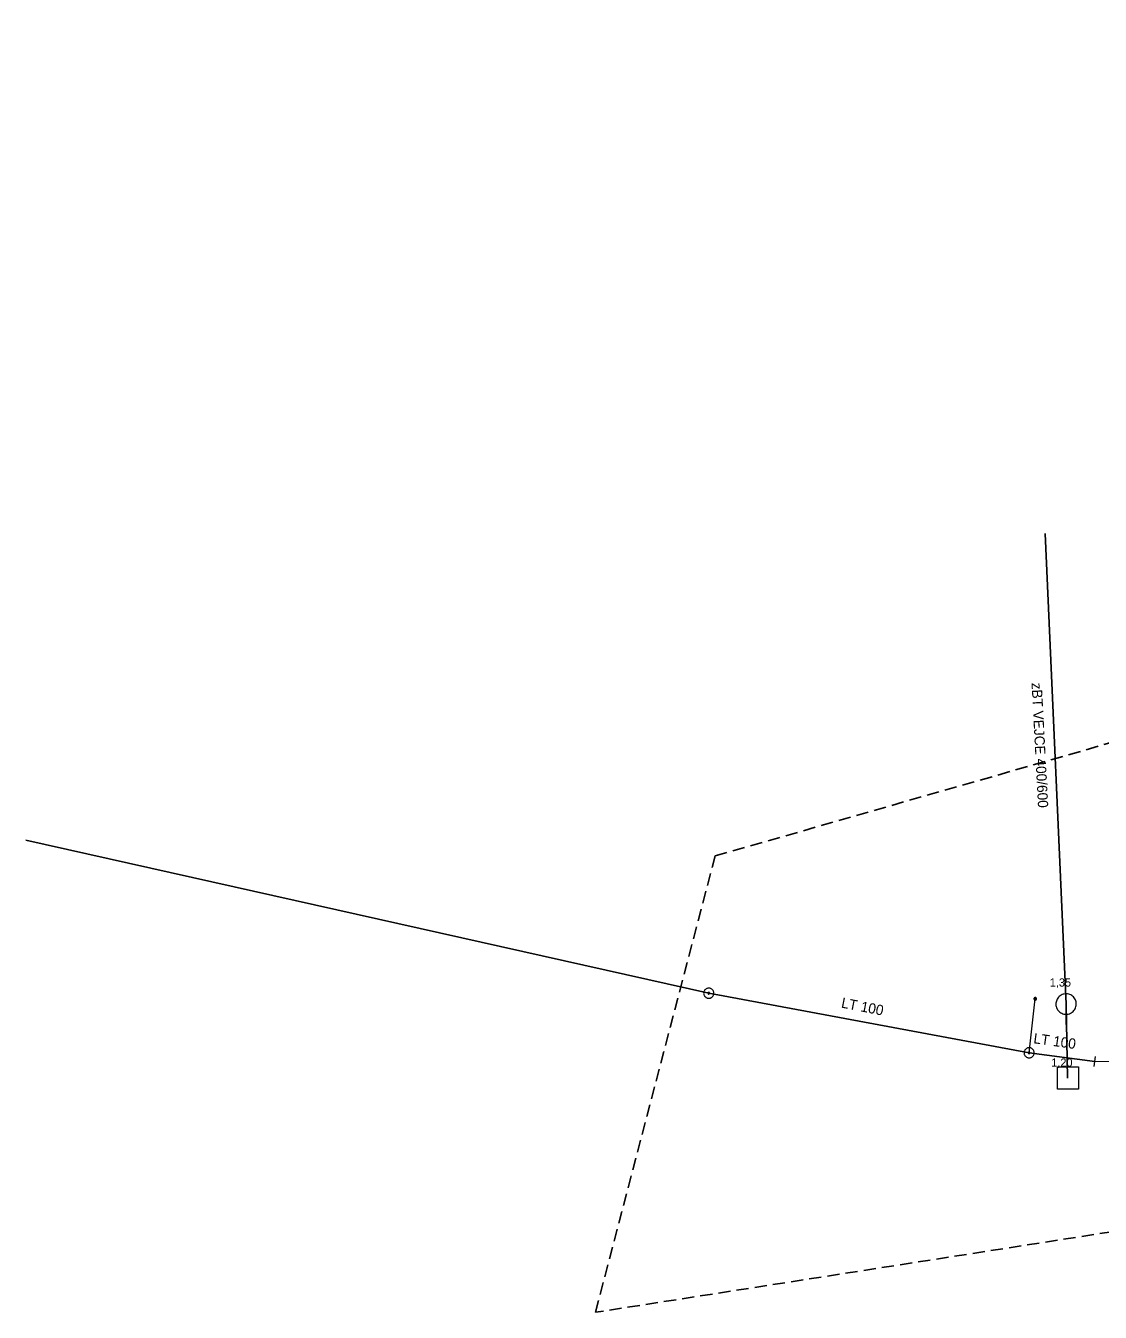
# Model space of a CAD drawing. Extents: x -689820 to -689363, y -975369 to -975062.
# Drawn here: x -689820.1 to -689714.8, y -975341.6 to -975215.7 of the extents above; entities that cross this region are included whole.
import ezdxf

# ---------------------------------------------------------------- set-up
doc = ezdxf.new("R2010")
doc.units = 0
doc.header["$LTSCALE"] = 0.4
doc.linetypes.add('MEDIUM_DASHED', pattern=[4.5, 3, -1.5])
doc.layers.add('1', color=7, linetype='Continuous')
for name, color, linetype, lineweight in [('14', 7, 'Continuous', 25), ('17', 7, 'Continuous', 25), ('22', 7, 'Continuous', 13), ('34', 7, 'Continuous', 13), ('47', 7, 'Continuous', 13), ('63', 7, 'MEDIUM_DASHED', 25), ('9', 7, 'Continuous', 13)]:
    doc.layers.add(name, color=color, linetype=linetype, lineweight=lineweight)

msp = doc.modelspace()

# ---------------------------------------------------------------- linework, layer by layer
at = {"layer": '14'}
for p, q in [((-689718.193, -975311.442), (-689720.241, -975265.388)), ((-689718.046, -975318.682), (-689718.193, -975311.442))]:
    msp.add_line(p, q, dxfattribs=at)
at = {"layer": '14', "lineweight": 13}
for p, q in [((-689721.813, -975316.213), (-689721.219, -975310.929)), ((-689713.89, -975317.113), (-689715.37, -975317.07))]:
    msp.add_line(p, q, dxfattribs=at)
at = {"layer": '17'}
for p, q in [((-689753.181, -975310.38), (-689820.059, -975295.399)), ((-689721.813, -975316.213), (-689753.181, -975310.38)), ((-689715.37, -975317.07), (-689721.813, -975316.213))]:
    msp.add_line(p, q, dxfattribs=at)
at = {"layer": '22'}
msp.add_line((-689718.193, -975313.442), (-689718.192, -975310.442), dxfattribs=at)
for points in [[(-689717.193, -975311.442), (-689717.198, -975311.333), (-689717.216, -975311.225), (-689717.246, -975311.119), (-689717.286, -975311.018), (-689717.338, -975310.921), (-689717.4, -975310.831), (-689717.472, -975310.748), (-689717.552, -975310.674), (-689717.64, -975310.608), (-689717.734, -975310.553), (-689717.834, -975310.508), (-689717.939, -975310.475), (-689718.046, -975310.453), (-689718.155, -975310.443), (-689718.265, -975310.445), (-689718.373, -975310.459), (-689718.48, -975310.484), (-689718.583, -975310.521), (-689718.681, -975310.57), (-689718.773, -975310.628), (-689718.859, -975310.697), (-689718.936, -975310.774), (-689719.005, -975310.86), (-689719.064, -975310.952), (-689719.112, -975311.05), (-689719.149, -975311.153), (-689719.175, -975311.26), (-689719.189, -975311.368), (-689719.192, -975311.478), (-689719.182, -975311.587), (-689719.161, -975311.694), (-689719.127, -975311.798), (-689719.083, -975311.898), (-689719.028, -975311.993), (-689718.962, -975312.081), (-689718.888, -975312.161), (-689718.805, -975312.233), (-689718.715, -975312.295), (-689718.619, -975312.347), (-689718.517, -975312.388), (-689718.412, -975312.418), (-689718.304, -975312.436), (-689718.194, -975312.442), (-689718.085, -975312.436), (-689717.977, -975312.418), (-689717.872, -975312.389), (-689717.77, -975312.348), (-689717.673, -975312.296), (-689717.583, -975312.234), (-689717.5, -975312.163), (-689717.425, -975312.083), (-689717.36, -975311.995), (-689717.304, -975311.901), (-689717.26, -975311.801), (-689717.226, -975311.697), (-689717.204, -975311.589), (-689717.194, -975311.48)], [(-689719.026, -975317.592), (-689716.993, -975317.592), (-689716.993, -975319.785), (-689719.026, -975319.785)]]:
    msp.add_lwpolyline(points, close=True, dxfattribs=at)
at = {"layer": '34'}
msp.add_line((-689715.435, -975317.565), (-689715.303, -975316.574), dxfattribs=at)
at = {"layer": '47'}
for points in [[(-689752.681, -975310.38), (-689752.684, -975310.328), (-689752.692, -975310.276), (-689752.706, -975310.226), (-689752.723, -975310.177), (-689752.748, -975310.13), (-689752.777, -975310.086), (-689752.809, -975310.046), (-689752.847, -975310.009), (-689752.887, -975309.976), (-689752.931, -975309.947), (-689752.978, -975309.923), (-689753.027, -975309.905), (-689753.076, -975309.891), (-689753.129, -975309.883), (-689753.181, -975309.88), (-689753.233, -975309.883), (-689753.285, -975309.891), (-689753.336, -975309.905), (-689753.384, -975309.923), (-689753.431, -975309.947), (-689753.475, -975309.976), (-689753.516, -975310.009), (-689753.553, -975310.046), (-689753.586, -975310.086), (-689753.614, -975310.13), (-689753.638, -975310.177), (-689753.657, -975310.226), (-689753.669, -975310.276), (-689753.678, -975310.328), (-689753.681, -975310.38), (-689753.678, -975310.432), (-689753.669, -975310.484), (-689753.657, -975310.535), (-689753.638, -975310.583), (-689753.614, -975310.63), (-689753.586, -975310.674), (-689753.553, -975310.715), (-689753.516, -975310.752), (-689753.475, -975310.785), (-689753.431, -975310.813), (-689753.384, -975310.837), (-689753.336, -975310.856), (-689753.285, -975310.869), (-689753.233, -975310.877), (-689753.181, -975310.88), (-689753.129, -975310.877), (-689753.076, -975310.869), (-689753.027, -975310.856), (-689752.978, -975310.837), (-689752.931, -975310.813), (-689752.887, -975310.785), (-689752.847, -975310.752), (-689752.809, -975310.715), (-689752.777, -975310.674), (-689752.748, -975310.63), (-689752.723, -975310.583), (-689752.706, -975310.535), (-689752.692, -975310.484), (-689752.684, -975310.432)], [(-689753.098, -975310.38), (-689753.098, -975310.371), (-689753.101, -975310.363), (-689753.103, -975310.355), (-689753.106, -975310.347), (-689753.11, -975310.339), (-689753.115, -975310.332), (-689753.12, -975310.325), (-689753.125, -975310.319), (-689753.133, -975310.314), (-689753.14, -975310.309), (-689753.147, -975310.305), (-689753.156, -975310.302), (-689753.164, -975310.3), (-689753.172, -975310.298), (-689753.181, -975310.298), (-689753.19, -975310.298), (-689753.198, -975310.3), (-689753.206, -975310.302), (-689753.214, -975310.305), (-689753.222, -975310.309), (-689753.228, -975310.314), (-689753.236, -975310.319), (-689753.242, -975310.325), (-689753.248, -975310.332), (-689753.252, -975310.339), (-689753.255, -975310.347), (-689753.259, -975310.355), (-689753.261, -975310.363), (-689753.263, -975310.371), (-689753.263, -975310.38), (-689753.263, -975310.389), (-689753.261, -975310.397), (-689753.259, -975310.405), (-689753.255, -975310.413), (-689753.252, -975310.421), (-689753.248, -975310.428), (-689753.242, -975310.435), (-689753.236, -975310.441), (-689753.228, -975310.447), (-689753.222, -975310.451), (-689753.214, -975310.455), (-689753.206, -975310.458), (-689753.198, -975310.46), (-689753.19, -975310.462), (-689753.181, -975310.462), (-689753.172, -975310.462), (-689753.164, -975310.46), (-689753.156, -975310.458), (-689753.147, -975310.455), (-689753.14, -975310.451), (-689753.133, -975310.447), (-689753.125, -975310.441), (-689753.12, -975310.435), (-689753.115, -975310.428), (-689753.11, -975310.421), (-689753.106, -975310.413), (-689753.103, -975310.405), (-689753.101, -975310.397), (-689753.098, -975310.389)], [(-689721.313, -975316.213), (-689721.316, -975316.161), (-689721.324, -975316.108), (-689721.338, -975316.059), (-689721.355, -975316.01), (-689721.38, -975315.963), (-689721.409, -975315.919), (-689721.441, -975315.879), (-689721.478, -975315.842), (-689721.519, -975315.809), (-689721.563, -975315.78), (-689721.61, -975315.755), (-689721.659, -975315.738), (-689721.708, -975315.724), (-689721.761, -975315.716), (-689721.813, -975315.713), (-689721.865, -975315.716), (-689721.917, -975315.724), (-689721.968, -975315.738), (-689722.016, -975315.755), (-689722.063, -975315.78), (-689722.107, -975315.809), (-689722.147, -975315.842), (-689722.184, -975315.879), (-689722.218, -975315.919), (-689722.245, -975315.963), (-689722.27, -975316.01), (-689722.289, -975316.059), (-689722.301, -975316.108), (-689722.309, -975316.161), (-689722.313, -975316.213), (-689722.309, -975316.265), (-689722.301, -975316.317), (-689722.289, -975316.368), (-689722.27, -975316.416), (-689722.245, -975316.463), (-689722.218, -975316.507), (-689722.184, -975316.548), (-689722.147, -975316.585), (-689722.107, -975316.618), (-689722.063, -975316.646), (-689722.016, -975316.67), (-689721.968, -975316.689), (-689721.917, -975316.701), (-689721.865, -975316.71), (-689721.813, -975316.713), (-689721.761, -975316.71), (-689721.708, -975316.701), (-689721.659, -975316.689), (-689721.61, -975316.67), (-689721.563, -975316.646), (-689721.519, -975316.618), (-689721.478, -975316.585), (-689721.441, -975316.548), (-689721.409, -975316.507), (-689721.38, -975316.463), (-689721.355, -975316.416), (-689721.338, -975316.368), (-689721.324, -975316.317), (-689721.316, -975316.265)], [(-689721.73, -975316.213), (-689721.73, -975316.204), (-689721.733, -975316.196), (-689721.735, -975316.188), (-689721.738, -975316.179), (-689721.742, -975316.172), (-689721.747, -975316.165), (-689721.752, -975316.157), (-689721.757, -975316.152), (-689721.765, -975316.147), (-689721.772, -975316.142), (-689721.779, -975316.138), (-689721.788, -975316.135), (-689721.796, -975316.133), (-689721.804, -975316.13), (-689721.813, -975316.13), (-689721.821, -975316.13), (-689721.83, -975316.133), (-689721.838, -975316.135), (-689721.846, -975316.138), (-689721.853, -975316.142), (-689721.86, -975316.147), (-689721.868, -975316.152), (-689721.874, -975316.157), (-689721.88, -975316.165), (-689721.884, -975316.172), (-689721.887, -975316.179), (-689721.891, -975316.188), (-689721.892, -975316.196), (-689721.895, -975316.204), (-689721.895, -975316.213), (-689721.895, -975316.222), (-689721.892, -975316.23), (-689721.891, -975316.238), (-689721.887, -975316.246), (-689721.884, -975316.254), (-689721.88, -975316.261), (-689721.874, -975316.268), (-689721.868, -975316.274), (-689721.86, -975316.28), (-689721.853, -975316.284), (-689721.846, -975316.288), (-689721.838, -975316.291), (-689721.83, -975316.293), (-689721.821, -975316.295), (-689721.813, -975316.295), (-689721.804, -975316.295), (-689721.796, -975316.293), (-689721.788, -975316.291), (-689721.779, -975316.288), (-689721.772, -975316.284), (-689721.765, -975316.28), (-689721.757, -975316.274), (-689721.752, -975316.268), (-689721.747, -975316.261), (-689721.742, -975316.254), (-689721.738, -975316.246), (-689721.735, -975316.238), (-689721.733, -975316.23), (-689721.73, -975316.222)]]:
    msp.add_lwpolyline(points, close=True, dxfattribs=at)
at = {"layer": '63'}
msp.add_lwpolyline([(-689662.123, -975114.404), (-689588.993, -975102.123), (-689588.993, -975102.123), (-689580.62, -975185.301), (-689580.62, -975185.301), (-689519.213, -975267.921), (-689519.213, -975267.921), (-689394.167, -975240.009), (-689394.167, -975240.009), (-689384.677, -975282.435), (-689384.677, -975282.435), (-689764.282, -975341.609), (-689764.282, -975341.609), (-689752.559, -975296.95), (-689752.559, -975296.95), (-689602.391, -975253.965), (-689627.512, -975210.422), (-689603.508, -975253.965), (-689648.167, -975167.437), (-689648.167, -975167.437)], close=True, dxfattribs=at)
at = {"layer": '9'}
for points in [[(-689721.345, -975310.929), (-689721.345, -975310.942), (-689721.343, -975310.955), (-689721.34, -975310.968), (-689721.335, -975310.98), (-689721.329, -975310.992), (-689721.322, -975311.003), (-689721.314, -975311.013), (-689721.304, -975311.023), (-689721.294, -975311.031), (-689721.283, -975311.038), (-689721.271, -975311.044), (-689721.259, -975311.049), (-689721.246, -975311.052), (-689721.233, -975311.054), (-689721.22, -975311.056), (-689721.207, -975311.055), (-689721.194, -975311.053), (-689721.181, -975311.05), (-689721.169, -975311.045), (-689721.157, -975311.039), (-689721.146, -975311.032), (-689721.136, -975311.024), (-689721.126, -975311.014), (-689721.118, -975311.004), (-689721.111, -975310.993), (-689721.105, -975310.981), (-689721.1, -975310.969), (-689721.097, -975310.956), (-689721.095, -975310.943), (-689721.093, -975310.93), (-689721.094, -975310.917), (-689721.096, -975310.904), (-689721.099, -975310.891), (-689721.104, -975310.879), (-689721.11, -975310.867), (-689721.117, -975310.856), (-689721.125, -975310.846), (-689721.135, -975310.836), (-689721.145, -975310.828), (-689721.156, -975310.821), (-689721.168, -975310.815), (-689721.18, -975310.81), (-689721.193, -975310.807), (-689721.206, -975310.805), (-689721.219, -975310.804), (-689721.232, -975310.804), (-689721.245, -975310.806), (-689721.258, -975310.809), (-689721.27, -975310.814), (-689721.282, -975310.82), (-689721.293, -975310.827), (-689721.303, -975310.835), (-689721.313, -975310.845), (-689721.321, -975310.855), (-689721.328, -975310.866), (-689721.334, -975310.878), (-689721.339, -975310.89), (-689721.342, -975310.903), (-689721.344, -975310.916)], [(-689721.325, -975310.929), (-689721.326, -975310.94), (-689721.324, -975310.951), (-689721.321, -975310.962), (-689721.317, -975310.972), (-689721.312, -975310.982), (-689721.306, -975310.991), (-689721.299, -975311), (-689721.291, -975311.008), (-689721.282, -975311.015), (-689721.273, -975311.021), (-689721.263, -975311.026), (-689721.253, -975311.03), (-689721.242, -975311.033), (-689721.231, -975311.036), (-689721.22, -975311.036), (-689721.209, -975311.036), (-689721.198, -975311.034), (-689721.187, -975311.031), (-689721.177, -975311.027), (-689721.167, -975311.022), (-689721.158, -975311.016), (-689721.149, -975311.009), (-689721.141, -975311.001), (-689721.134, -975310.992), (-689721.128, -975310.983), (-689721.123, -975310.973), (-689721.119, -975310.963), (-689721.116, -975310.952), (-689721.114, -975310.941), (-689721.113, -975310.93), (-689721.113, -975310.919), (-689721.115, -975310.908), (-689721.118, -975310.897), (-689721.122, -975310.887), (-689721.127, -975310.877), (-689721.133, -975310.868), (-689721.14, -975310.859), (-689721.148, -975310.851), (-689721.157, -975310.844), (-689721.166, -975310.838), (-689721.176, -975310.833), (-689721.186, -975310.829), (-689721.197, -975310.826), (-689721.208, -975310.824), (-689721.219, -975310.824), (-689721.23, -975310.823), (-689721.241, -975310.825), (-689721.252, -975310.828), (-689721.262, -975310.832), (-689721.272, -975310.837), (-689721.281, -975310.843), (-689721.29, -975310.85), (-689721.298, -975310.858), (-689721.305, -975310.867), (-689721.311, -975310.876), (-689721.316, -975310.886), (-689721.32, -975310.896), (-689721.323, -975310.907), (-689721.325, -975310.918)], [(-689721.306, -975310.929), (-689721.306, -975310.938), (-689721.305, -975310.947), (-689721.302, -975310.956), (-689721.299, -975310.964), (-689721.295, -975310.972), (-689721.29, -975310.98), (-689721.284, -975310.987), (-689721.278, -975310.993), (-689721.271, -975310.999), (-689721.263, -975311.004), (-689721.255, -975311.008), (-689721.247, -975311.011), (-689721.238, -975311.014), (-689721.229, -975311.015), (-689721.22, -975311.017), (-689721.211, -975311.016), (-689721.202, -975311.015), (-689721.193, -975311.012), (-689721.185, -975311.009), (-689721.177, -975311.005), (-689721.169, -975311), (-689721.162, -975310.994), (-689721.156, -975310.988), (-689721.15, -975310.981), (-689721.145, -975310.973), (-689721.141, -975310.965), (-689721.138, -975310.957), (-689721.135, -975310.948), (-689721.134, -975310.939), (-689721.132, -975310.93), (-689721.133, -975310.921), (-689721.134, -975310.912), (-689721.137, -975310.903), (-689721.14, -975310.895), (-689721.144, -975310.887), (-689721.149, -975310.879), (-689721.155, -975310.872), (-689721.161, -975310.866), (-689721.168, -975310.86), (-689721.176, -975310.855), (-689721.184, -975310.851), (-689721.192, -975310.848), (-689721.201, -975310.845), (-689721.21, -975310.844), (-689721.219, -975310.843), (-689721.228, -975310.843), (-689721.237, -975310.844), (-689721.246, -975310.847), (-689721.254, -975310.85), (-689721.262, -975310.854), (-689721.27, -975310.859), (-689721.277, -975310.865), (-689721.283, -975310.871), (-689721.289, -975310.878), (-689721.294, -975310.886), (-689721.298, -975310.894), (-689721.301, -975310.902), (-689721.304, -975310.911), (-689721.305, -975310.92)], [(-689721.286, -975310.929), (-689721.286, -975310.936), (-689721.285, -975310.943), (-689721.284, -975310.95), (-689721.281, -975310.956), (-689721.278, -975310.962), (-689721.274, -975310.968), (-689721.27, -975310.974), (-689721.265, -975310.979), (-689721.259, -975310.983), (-689721.253, -975310.987), (-689721.247, -975310.99), (-689721.241, -975310.993), (-689721.234, -975310.994), (-689721.227, -975310.997), (-689721.22, -975310.997), (-689721.213, -975310.997), (-689721.206, -975310.995), (-689721.199, -975310.994), (-689721.193, -975310.991), (-689721.186, -975310.988), (-689721.181, -975310.984), (-689721.175, -975310.98), (-689721.17, -975310.975), (-689721.166, -975310.969), (-689721.162, -975310.963), (-689721.159, -975310.957), (-689721.156, -975310.951), (-689721.154, -975310.944), (-689721.153, -975310.937), (-689721.152, -975310.93), (-689721.152, -975310.923), (-689721.153, -975310.916), (-689721.155, -975310.909), (-689721.158, -975310.903), (-689721.161, -975310.896), (-689721.165, -975310.891), (-689721.169, -975310.885), (-689721.174, -975310.88), (-689721.18, -975310.876), (-689721.185, -975310.872), (-689721.192, -975310.869), (-689721.198, -975310.866), (-689721.205, -975310.864), (-689721.212, -975310.863), (-689721.219, -975310.863), (-689721.226, -975310.863), (-689721.233, -975310.863), (-689721.24, -975310.865), (-689721.246, -975310.868), (-689721.252, -975310.871), (-689721.258, -975310.875), (-689721.264, -975310.879), (-689721.269, -975310.884), (-689721.273, -975310.89), (-689721.277, -975310.895), (-689721.28, -975310.902), (-689721.283, -975310.908), (-689721.284, -975310.915), (-689721.286, -975310.922)], [(-689721.266, -975310.929), (-689721.266, -975310.934), (-689721.266, -975310.939), (-689721.265, -975310.944), (-689721.263, -975310.948), (-689721.261, -975310.953), (-689721.258, -975310.957), (-689721.255, -975310.96), (-689721.251, -975310.964), (-689721.248, -975310.967), (-689721.244, -975310.97), (-689721.239, -975310.972), (-689721.235, -975310.974), (-689721.23, -975310.975), (-689721.225, -975310.977), (-689721.22, -975310.977), (-689721.215, -975310.977), (-689721.21, -975310.976), (-689721.205, -975310.975), (-689721.201, -975310.973), (-689721.196, -975310.971), (-689721.192, -975310.968), (-689721.188, -975310.965), (-689721.185, -975310.961), (-689721.182, -975310.958), (-689721.179, -975310.954), (-689721.177, -975310.949), (-689721.175, -975310.945), (-689721.174, -975310.94), (-689721.173, -975310.935), (-689721.172, -975310.93), (-689721.172, -975310.925), (-689721.173, -975310.92), (-689721.174, -975310.915), (-689721.176, -975310.911), (-689721.178, -975310.906), (-689721.181, -975310.902), (-689721.184, -975310.898), (-689721.187, -975310.895), (-689721.191, -975310.892), (-689721.195, -975310.889), (-689721.2, -975310.887), (-689721.204, -975310.885), (-689721.209, -975310.884), (-689721.214, -975310.883), (-689721.219, -975310.883), (-689721.224, -975310.883), (-689721.229, -975310.884), (-689721.234, -975310.884), (-689721.238, -975310.886), (-689721.243, -975310.888), (-689721.247, -975310.891), (-689721.25, -975310.894), (-689721.254, -975310.897), (-689721.257, -975310.901), (-689721.26, -975310.905), (-689721.262, -975310.91), (-689721.264, -975310.914), (-689721.265, -975310.919), (-689721.266, -975310.924)], [(-689721.246, -975310.929), (-689721.246, -975310.932), (-689721.247, -975310.935), (-689721.246, -975310.937), (-689721.245, -975310.94), (-689721.244, -975310.943), (-689721.242, -975310.945), (-689721.24, -975310.947), (-689721.238, -975310.949), (-689721.236, -975310.951), (-689721.234, -975310.953), (-689721.231, -975310.955), (-689721.228, -975310.956), (-689721.226, -975310.956), (-689721.223, -975310.957), (-689721.22, -975310.957), (-689721.217, -975310.957), (-689721.214, -975310.957), (-689721.211, -975310.956), (-689721.209, -975310.955), (-689721.206, -975310.954), (-689721.204, -975310.952), (-689721.201, -975310.95), (-689721.199, -975310.948), (-689721.198, -975310.946), (-689721.196, -975310.944), (-689721.195, -975310.941), (-689721.193, -975310.938), (-689721.193, -975310.936), (-689721.192, -975310.933), (-689721.191, -975310.93), (-689721.192, -975310.927), (-689721.192, -975310.924), (-689721.193, -975310.921), (-689721.194, -975310.919), (-689721.195, -975310.916), (-689721.197, -975310.914), (-689721.198, -975310.911), (-689721.2, -975310.909), (-689721.203, -975310.908), (-689721.205, -975310.906), (-689721.208, -975310.905), (-689721.21, -975310.904), (-689721.213, -975310.903), (-689721.216, -975310.903), (-689721.219, -975310.902), (-689721.222, -975310.903), (-689721.225, -975310.902), (-689721.227, -975310.904), (-689721.23, -975310.904), (-689721.233, -975310.905), (-689721.235, -975310.907), (-689721.237, -975310.908), (-689721.239, -975310.91), (-689721.241, -975310.913), (-689721.243, -975310.915), (-689721.244, -975310.918), (-689721.245, -975310.92), (-689721.246, -975310.923), (-689721.246, -975310.926)], [(-689721.227, -975310.929), (-689721.227, -975310.931), (-689721.227, -975310.931), (-689721.226, -975310.931), (-689721.226, -975310.933), (-689721.227, -975310.934), (-689721.225, -975310.934), (-689721.225, -975310.934), (-689721.225, -975310.936), (-689721.225, -975310.936), (-689721.224, -975310.937), (-689721.222, -975310.937), (-689721.222, -975310.937), (-689721.222, -975310.938), (-689721.22, -975310.938), (-689721.22, -975310.938), (-689721.219, -975310.938), (-689721.218, -975310.938), (-689721.218, -975310.937), (-689721.217, -975310.937), (-689721.215, -975310.937), (-689721.215, -975310.936), (-689721.215, -975310.936), (-689721.214, -975310.935), (-689721.214, -975310.935), (-689721.212, -975310.934), (-689721.212, -975310.933), (-689721.211, -975310.932), (-689721.211, -975310.932), (-689721.211, -975310.931), (-689721.211, -975310.93), (-689721.211, -975310.929), (-689721.211, -975310.928), (-689721.211, -975310.928), (-689721.212, -975310.927), (-689721.212, -975310.926), (-689721.213, -975310.925), (-689721.213, -975310.925), (-689721.214, -975310.924), (-689721.214, -975310.924), (-689721.215, -975310.923), (-689721.216, -975310.923), (-689721.217, -975310.922), (-689721.217, -975310.922), (-689721.218, -975310.922), (-689721.219, -975310.922), (-689721.22, -975310.922), (-689721.221, -975310.922), (-689721.221, -975310.922), (-689721.222, -975310.923), (-689721.223, -975310.922), (-689721.224, -975310.924), (-689721.224, -975310.924), (-689721.225, -975310.924), (-689721.225, -975310.924), (-689721.226, -975310.926), (-689721.226, -975310.927), (-689721.226, -975310.928), (-689721.227, -975310.928), (-689721.227, -975310.929)]]:
    msp.add_lwpolyline(points, close=True, dxfattribs=at)

# ---------------------------------------------------------------- texts
at = {"layer": '1'}
for s, rotation, p in [('zBT VEJCE 400/600 ', 273, (-689721.577, -975280.011)), ('LT 100', 349, (-689740.265, -975311.779)), ('LT 100', 352, (-689721.434, -975315.269))]:
    msp.add_text(s, height=1, rotation=rotation, dxfattribs=at).set_placement(p)
for s, p in [('1,35', (-689719.793, -975309.73)), ('1,20', (-689719.646, -975317.567))]:
    msp.add_text(s, height=0.8, dxfattribs=at).set_placement(p)

doc.saveas('drawing.dxf')
